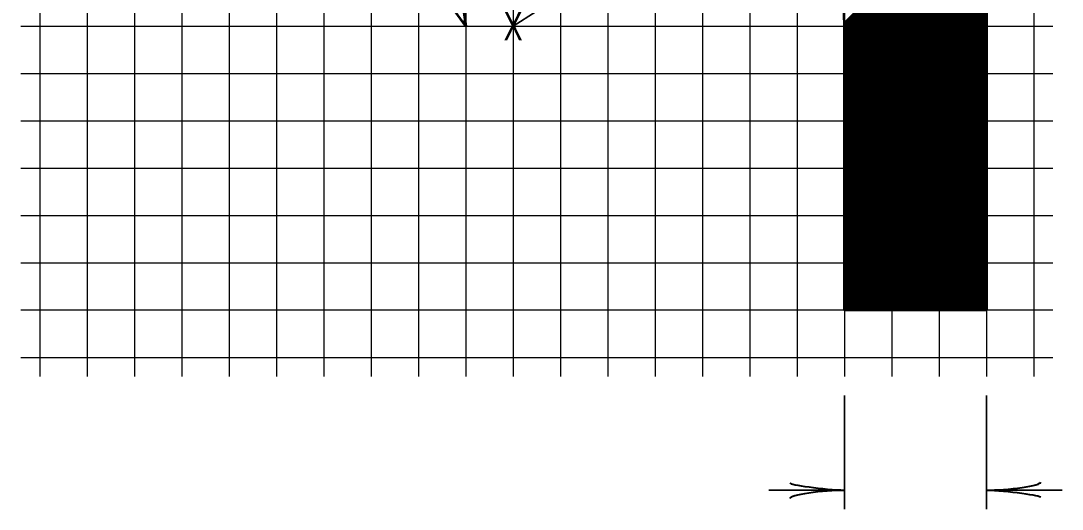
# Model space of a CAD drawing. Extents: x -96 to 617, y -65 to 388.
# Drawn here: x 175.6 to 230.6, y 130.6 to 156.4 of the extents above; entities that cross this region are included whole.
import ezdxf
from ezdxf.enums import TextEntityAlignment as Align

# ---------------------------------------------------------------- set-up
doc = ezdxf.new("R2010")
doc.units = 0
doc.layers.add('1', color=7, linetype='Continuous', lineweight=53)

msp = doc.modelspace()

# ---------------------------------------------------------------- linework, layer by layer
at = {"layer": '1', "lineweight": 25}
for p, q in [((176.579, 207.099), (176.579, 137.599)), ((179.079, 207.099), (179.079, 137.599)), ((181.579, 207.099), (181.579, 137.599)), ((184.079, 207.099), (184.079, 137.599)), ((186.579, 207.099), (186.579, 137.599)), ((189.079, 207.099), (189.079, 137.599)), ((191.579, 207.099), (191.579, 137.599)), ((194.079, 207.099), (194.079, 137.599)), ((196.579, 207.099), (196.579, 137.599)), ((199.079, 207.099), (199.079, 137.599)), ((216.579, 207.099), (216.579, 137.599)), ((219.079, 207.099), (219.079, 137.599)), ((221.579, 207.099), (221.579, 137.599)), ((224.079, 207.099), (224.079, 137.599)), ((226.579, 207.099), (226.579, 137.599)), ((229.079, 207.099), (229.079, 137.599)), ((214.079, 163.336), (214.079, 137.599)), ((201.579, 162.516), (201.579, 137.599)), ((211.579, 162.115), (211.579, 137.599)), ((209.079, 160.672), (209.079, 137.599)), ((206.579, 159.081), (206.579, 137.599)), ((204.079, 157.305), (204.079, 137.599)), ((175.579, 156.099), (199.079, 156.099)), ((199.079, 156.099), (201.579, 156.099)), ((175.579, 153.599), (230.079, 153.599)), ((175.579, 151.099), (230.079, 151.099)), ((175.579, 148.599), (230.079, 148.599)), ((175.579, 146.099), (230.079, 146.099)), ((175.579, 143.599), (230.079, 143.599)), ((230.079, 141.099), (175.579, 141.099)), ((175.579, 138.599), (230.079, 138.599))]:
    msp.add_line(p, q, dxfattribs=at)
at = {"layer": '1', "lineweight": 35}
for p, q in [((216.337, 165.591), (201.579, 156.099)), ((226.579, 163.599), (226.579, 141.099)), ((219.079, 136.599), (219.079, 130.599)), ((226.579, 136.599), (226.579, 130.599)), ((215.079, 131.599), (219.079, 131.599)), ((226.579, 131.599), (230.579, 131.599))]:
    msp.add_line(p, q, dxfattribs=at)
at = {"layer": '1'}
for p, q in [((219.077, 156.268), (226.573, 163.763)), ((219.079, 156.093), (226.579, 163.593)), ((219.079, 155.916), (226.579, 163.416)), ((219.079, 155.739), (226.579, 163.239)), ((219.079, 155.562), (226.579, 163.062)), ((219.079, 155.386), (226.579, 162.886)), ((219.079, 155.209), (226.579, 162.709)), ((219.079, 155.032), (226.579, 162.532)), ((219.079, 154.855), (226.579, 162.355)), ((219.079, 154.678), (226.579, 162.178)), ((219.079, 154.502), (226.579, 162.002)), ((219.079, 154.325), (226.579, 161.825)), ((219.079, 154.148), (226.579, 161.648)), ((219.079, 153.971), (226.579, 161.471)), ((219.079, 153.795), (226.579, 161.295)), ((219.079, 153.618), (226.579, 161.118)), ((219.079, 153.441), (226.579, 160.941)), ((219.079, 153.264), (226.579, 160.764)), ((219.079, 153.087), (226.579, 160.587)), ((219.079, 152.911), (226.579, 160.411)), ((219.079, 152.734), (226.579, 160.234)), ((219.079, 152.557), (226.579, 160.057)), ((219.079, 152.38), (226.579, 159.88)), ((219.079, 152.204), (226.579, 159.704)), ((219.079, 152.027), (226.579, 159.527)), ((219.079, 151.85), (226.579, 159.35)), ((219.079, 151.673), (226.579, 159.173)), ((219.079, 151.496), (226.579, 158.996)), ((219.079, 151.32), (226.579, 158.82)), ((219.079, 151.143), (226.579, 158.643)), ((219.079, 150.966), (226.579, 158.466)), ((219.079, 150.789), (226.579, 158.289)), ((219.079, 150.613), (226.579, 158.113)), ((219.079, 150.436), (226.579, 157.936)), ((219.079, 150.259), (226.579, 157.759)), ((219.079, 150.082), (226.579, 157.582)), ((219.079, 149.905), (226.579, 157.405)), ((219.079, 149.729), (226.579, 157.229)), ((219.079, 149.552), (226.579, 157.052)), ((219.079, 149.375), (226.579, 156.875)), ((198.942, 156.286), (199.038, 156.381)), ((199.017, 156.183), (199.06, 156.227)), ((219.079, 149.198), (226.579, 156.698)), ((219.079, 149.022), (226.579, 156.522)), ((219.079, 148.845), (226.579, 156.345)), ((219.079, 148.668), (226.579, 156.168)), ((219.079, 141.099), (219.079, 156.099)), ((219.079, 148.491), (226.579, 155.991)), ((219.079, 148.314), (226.579, 155.814)), ((219.079, 148.138), (226.579, 155.638)), ((219.079, 147.961), (226.579, 155.461)), ((219.079, 147.784), (226.579, 155.284)), ((219.079, 147.607), (226.579, 155.107)), ((219.079, 147.431), (226.579, 154.931)), ((219.079, 147.254), (226.579, 154.754)), ((219.079, 147.077), (226.579, 154.577)), ((219.079, 146.9), (226.579, 154.4)), ((219.079, 146.724), (226.579, 154.224)), ((219.079, 146.547), (226.579, 154.047)), ((219.079, 146.37), (226.579, 153.87)), ((219.079, 146.193), (226.579, 153.693)), ((219.079, 146.016), (226.579, 153.516)), ((219.079, 145.84), (226.579, 153.34)), ((219.079, 145.663), (226.579, 153.163)), ((219.079, 145.486), (226.579, 152.986)), ((219.079, 145.309), (226.579, 152.809)), ((219.079, 145.132), (226.579, 152.632)), ((219.079, 144.956), (226.579, 152.456)), ((219.079, 144.779), (226.579, 152.279)), ((219.079, 144.602), (226.579, 152.102)), ((219.079, 144.425), (226.579, 151.925)), ((219.079, 144.249), (226.579, 151.749)), ((219.079, 144.072), (226.579, 151.572)), ((219.079, 143.895), (226.579, 151.395)), ((219.079, 143.718), (226.579, 151.218)), ((219.079, 143.541), (226.579, 151.041)), ((219.079, 143.365), (226.579, 150.865)), ((219.079, 143.188), (226.579, 150.688)), ((219.079, 143.011), (226.579, 150.511)), ((219.079, 142.834), (226.579, 150.334)), ((219.079, 142.658), (226.579, 150.158)), ((219.079, 142.481), (226.579, 149.981)), ((219.079, 142.304), (226.579, 149.804)), ((219.079, 142.127), (226.579, 149.627)), ((219.079, 141.951), (226.579, 149.451)), ((219.079, 141.774), (226.579, 149.274)), ((219.079, 141.597), (226.579, 149.097)), ((219.079, 141.42), (226.579, 148.92)), ((219.079, 141.243), (226.579, 148.743)), ((219.111, 141.099), (226.579, 148.567)), ((219.287, 141.099), (226.579, 148.39)), ((219.464, 141.099), (226.579, 148.213)), ((219.641, 141.099), (226.579, 148.036)), ((219.818, 141.099), (226.579, 147.859)), ((219.994, 141.099), (226.579, 147.683)), ((220.171, 141.099), (226.579, 147.506)), ((220.348, 141.099), (226.579, 147.329)), ((220.525, 141.099), (226.579, 147.152)), ((220.701, 141.099), (226.579, 146.976)), ((220.878, 141.099), (226.579, 146.799)), ((221.055, 141.099), (226.579, 146.622)), ((221.232, 141.099), (226.579, 146.445)), ((221.409, 141.099), (226.579, 146.268)), ((221.585, 141.099), (226.579, 146.092)), ((221.762, 141.099), (226.579, 145.915)), ((221.939, 141.099), (226.579, 145.738)), ((222.116, 141.099), (226.579, 145.561)), ((222.292, 141.099), (226.579, 145.385)), ((222.469, 141.099), (226.579, 145.208)), ((222.646, 141.099), (226.579, 145.031)), ((222.823, 141.099), (226.579, 144.854)), ((223, 141.099), (226.579, 144.678)), ((223.176, 141.099), (226.579, 144.501)), ((223.353, 141.099), (226.579, 144.324)), ((223.53, 141.099), (226.579, 144.147)), ((223.707, 141.099), (226.579, 143.97)), ((223.883, 141.099), (226.579, 143.794)), ((224.06, 141.099), (226.579, 143.617)), ((224.237, 141.099), (226.579, 143.44)), ((224.414, 141.099), (226.579, 143.263)), ((224.591, 141.099), (226.579, 143.087)), ((224.767, 141.099), (226.579, 142.91)), ((224.944, 141.099), (226.579, 142.733)), ((225.121, 141.099), (226.579, 142.556)), ((225.298, 141.099), (226.579, 142.379)), ((225.475, 141.099), (226.579, 142.203)), ((225.651, 141.099), (226.579, 142.026)), ((225.828, 141.099), (226.579, 141.849)), ((226.005, 141.099), (226.579, 141.672)), ((226.182, 141.099), (226.579, 141.496)), ((226.358, 141.099), (226.579, 141.319)), ((226.535, 141.099), (226.579, 141.142))]:
    msp.add_line(p, q, dxfattribs=at)
for points in [[(204.079, 173.599), (196.579, 173.599), (199.079, 156.099), (179.079, 183.599)], [(226.579, 163.599), (226.579, 141.099), (219.079, 141.099), (219.079, 156.099)]]:
    msp.add_lwpolyline(points, dxfattribs=at)
at = {"layer": '1', "lineweight": 25}
msp.add_lwpolyline([(201.579, 156.099), (203.445, 156.099), (230.079, 156.099)], dxfattribs=at)
at = {"layer": '1'}
msp.add_arc((201.418, 156.14), 17.66, 359.8661, 64.8424, dxfattribs=at)
at = {"layer": '1', "lineweight": 40}
for centre, major_axis, ratio, start_param, end_param in [((227.67, 131.875), (-1.786, -0.156), 0.122415, 0.896353, 3.141593), ((227.67, 131.875), (-1.786, -0.156), 0.122415, 0.896353, 3.141593), ((217.987, 131.322), (1.786, 0.156), 0.122415, 0.896353, 3.141593), ((217.987, 131.322), (1.786, 0.156), 0.122415, 0.896353, 3.141593), ((217.958, 131.81), (1.756, -0.176), 0.07063, 3.140715, 5.41811), ((217.958, 131.81), (1.756, -0.176), 0.07063, 3.140715, 5.41811), ((227.699, 131.387), (-1.756, 0.176), 0.07063, 3.140715, 5.41811), ((227.699, 131.387), (-1.756, 0.176), 0.07063, 3.140715, 5.41811)]:
    msp.add_ellipse(centre, major_axis=major_axis, ratio=ratio, start_param=start_param, end_param=end_param, dxfattribs=at)

# ---------------------------------------------------------------- texts
at = {"layer": '1', "width": 0.75}
msp.add_text('X', height=1.5, dxfattribs=at).set_placement((201.579, 155.349), align=Align.CENTER)

doc.saveas('drawing.dxf')
